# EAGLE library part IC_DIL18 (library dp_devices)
Universal 18pins IC
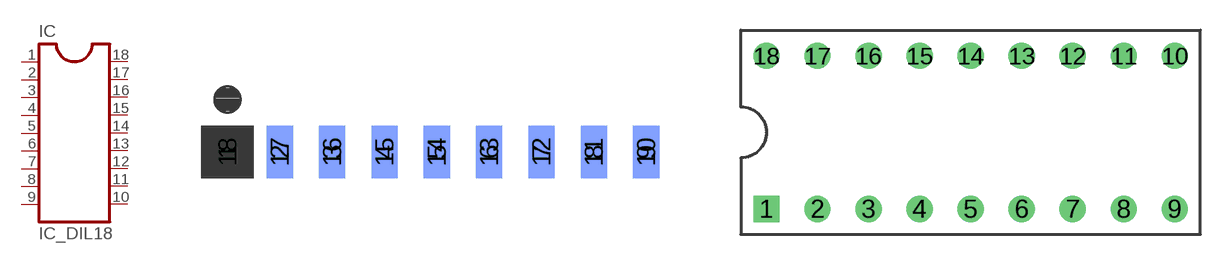
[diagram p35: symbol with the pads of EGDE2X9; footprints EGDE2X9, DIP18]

Designator prefix IC

## IC_DIL18-EDGE  [EGDE2X9]
1  1
2  2
3  3
4  4
5  5
6  6
7  7
8  8
9  9
10  10
11  11
12  12
13  13
14  14
15  15
16  16
17  17
18  18

## IC_DIL18-PTH  [DIP18]
Pads as for EGDE2X9

## Footprint EGDE2X9 (pad centres in mm)
smd 1.27 x 2.54: 1 -10.16,0; 2 -7.62,0; 3 -5.08,0; 4 -2.54,0; 5 0,0; 6 2.54,0; 7 5.08,0; 8 7.62,0; 9 10.16,0
smd 1.27 x 2.54 bottom: 10 10.16,0; 11 7.62,0; 12 5.08,0; 13 2.54,0; 14 0,0; 15 -2.54,0; 16 -5.08,0; 17 -7.62,0; 18 -10.16,0

## Footprint DIP18 (pad centres in mm)
drill 0.8 square: 1 -10.16,-3.81
drill 0.8 round: 2 -7.62,-3.81; 3 -5.08,-3.81; 4 -2.54,-3.81; 5 0,-3.81; 6 2.54,-3.81; 7 5.08,-3.81; 8 7.62,-3.81; 9 10.16,-3.81; 10 10.16,3.81; 11 7.62,3.81; 12 5.08,3.81; 13 2.54,3.81; 14 0,3.81; 15 -2.54,3.81; 16 -5.08,3.81; 17 -7.62,3.81; 18 -10.16,3.81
